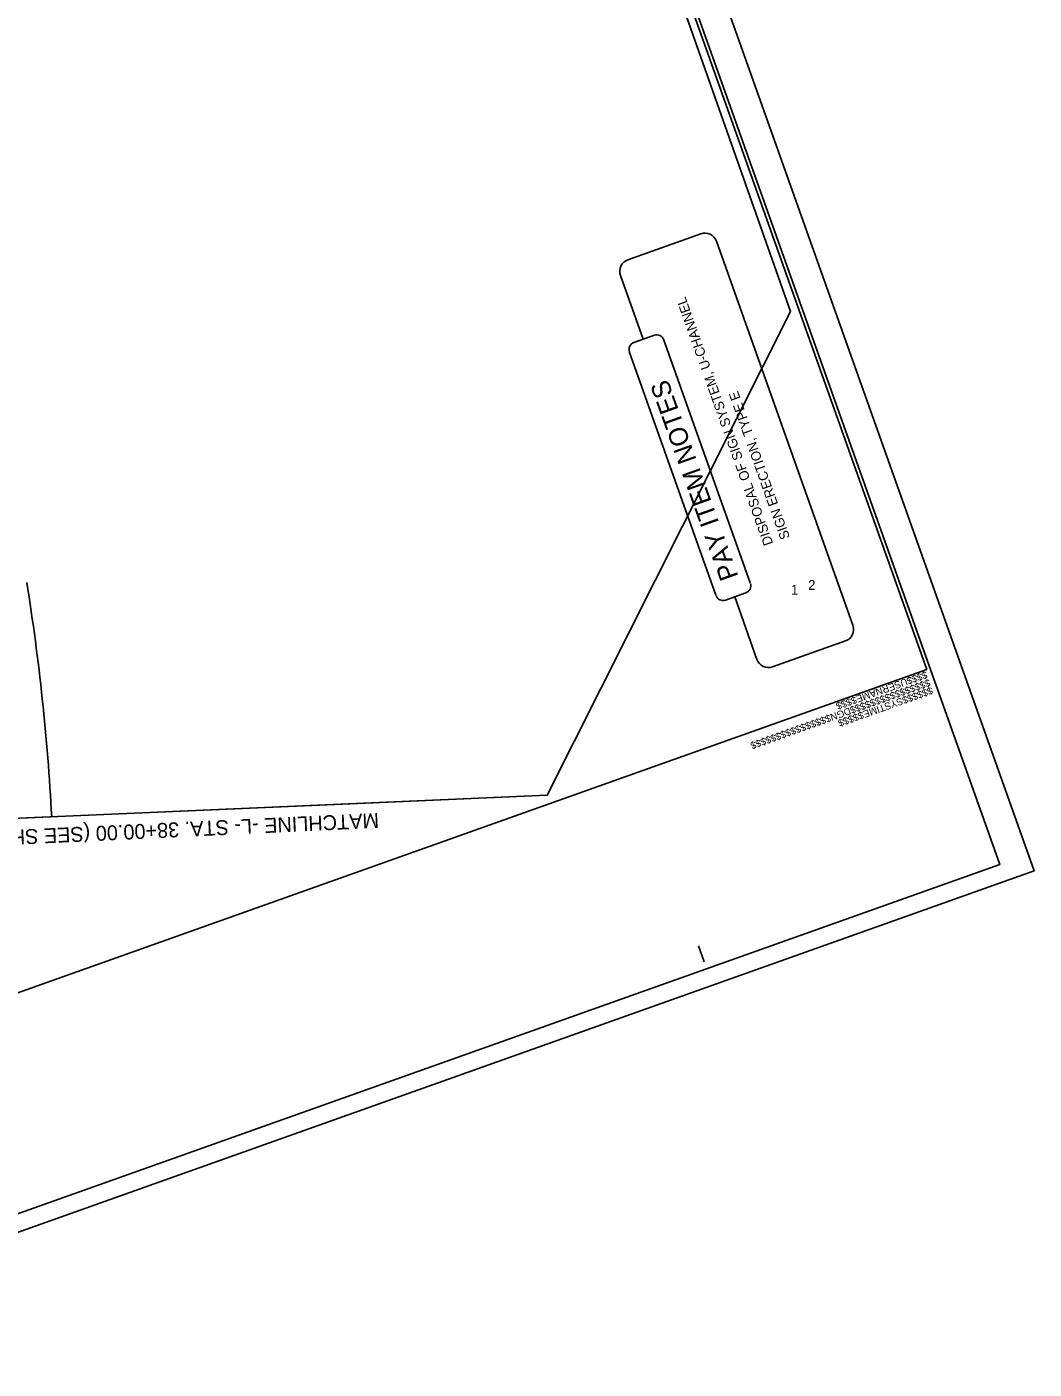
# Model space of a CAD drawing. Extents: x 1615843 to 1617444, y 901966 to 903921.
# Drawn here: x 1616698 to 1617444, y 901966 to 902958 of the extents above; entities that cross this region are included whole.
import ezdxf

# ---------------------------------------------------------------- set-up
doc = ezdxf.new("R2010")
doc.units = 0
for name, color, linetype in [('CTL Primary Horizontal and Vertical CELL', 7, 'Continuous'), ('CTL Primary Horizontal and Vertical Cogo Number', 7, 'Continuous'), ('CTL Secondary Horizontal and Vertical CELL', 7, 'Continuous'), ('Default', 7, 'Continuous'), ('Exist DTM Crownline Cogo Point CELL', 7, 'Continuous'), ('Exist DTM Regular Point CELL', 7, 'Continuous'), ('Exist Roads Curbs Cogo Number', 7, 'Continuous'), ('Exist Roads Curbs Cogo Point CELL', 7, 'Continuous'), ('Exist Structure Minor Pipes RCP 15 Inch Cogo Point CELL', 7, 'Continuous')]:
    doc.layers.add(name, color=color, linetype=linetype)

msp = doc.modelspace()

# ---------------------------------------------------------------- linework, layer by layer
at = {"layer": 'CTL Primary Horizontal and Vertical CELL'}
msp.add_lwpolyline([(1615865.68, 903555.66), (1616423.91, 901985.43), (1617418.05, 902338.86), (1616859.83, 903909.09)], close=True, dxfattribs=at)
at = {"layer": 'CTL Primary Horizontal and Vertical Cogo Number'}
msp.add_lwpolyline([(1615843.02, 903552.38), (1616407.11, 901965.67), (1617443.56, 902334.13), (1616879.47, 903920.85)], close=True, dxfattribs=at)
at = {"layer": 'CTL Secondary Horizontal and Vertical CELL'}
msp.add_line((1617199.45, 902266.98), (1617195.26, 902278.76), dxfattribs=at)
msp.add_lwpolyline([(1615872.27, 903544.74), (1616374.72, 902131.39), (1617364.06, 902483.11), (1616861.61, 903896.45)], close=True, dxfattribs=at)
at = {"layer": 'Exist DTM Crownline Cogo Point CELL'}
msp.add_lwpolyline([(1616920.55, 902382.99), (1616299.46, 902356.07), (1615953.12, 903334.31), (1616369.18, 903520.6), (1616903.33, 903759.78), (1617120.19, 903154.34), (1617263.37, 902747.79), (1617083.45, 902390.05)], close=True, dxfattribs=at)
at = {"layer": 'Exist DTM Regular Point CELL'}
msp.add_arc((1615052.19, 902285.31), 1667.02, 3.05543, 9.05, dxfattribs=at)
at = {"layer": 'Exist Roads Curbs Cogo Point CELL'}
msp.add_line((1616299.46, 902356.07), (1617083.45, 902390.05), dxfattribs=at)
at = {"layer": 'Exist Structure Minor Pipes RCP 15 Inch Cogo Point CELL'}
for p, q in [((1617196.98, 902805.27), (1617143.08, 902786.11)), ((1617309.54, 902515.8), (1617208.59, 902799.75)), ((1617154.33, 902727.33), (1617137.56, 902774.5)), ((1617162.61, 902730.28), (1617147.51, 902724.91)), ((1617230.33, 902539.8), (1617215.23, 902534.43)), ((1617238.51, 902490.55), (1617222.04, 902536.85)), ((1617304.02, 902504.19), (1617250.11, 902485.03))]:
    msp.add_line(p, q, dxfattribs=at)
for points in [[(1617233.49, 902547.19), (1617169.42, 902727.4)], [(1617208.11, 902538.17), (1617144.05, 902718.38)]]:
    msp.add_lwpolyline(points, dxfattribs=at)
for centre, radius, start, end in [((1617200.03, 902796.71), 9.09, 19.57069, 109.57069), ((1617146.12, 902777.54), 9.09, 109.57069, 199.57069), ((1617164.44, 902725.14), 5.45, 19.57069, 109.57069), ((1617149.34, 902719.77), 5.45, 109.57069, 199.57069), ((1617228.5, 902544.93), 5.45, 289.57069, 19.57069), ((1617213.4, 902539.57), 5.45, 199.57069, 289.57069), ((1617300.97, 902512.76), 9.09, 289.57069, 19.57069), ((1617247.07, 902493.59), 9.09, 199.57069, 289.57069)]:
    msp.add_arc(centre, radius, start, end, dxfattribs=at)

# ---------------------------------------------------------------- texts
at = {"layer": 'CTL Secondary Horizontal and Vertical CELL'}
for s, p in [('$$$$USERNAME$$$$', (1617363.45, 902481.99)), ('$$$$$$$$$$$$$$$$DGN$$$$$$$$$$$$$$$$', (1617365.66, 902476.09)), ('$$$$$$SYSTIME$$$$$', (1617367.5, 902470.32))]:
    msp.add_text(s, height=5.25, rotation=199.57069, dxfattribs=at).set_placement(p)
at = {"layer": 'Default'}
for s, height, rotation, p in [('DISPOSAL OF SIGN SYSTEM, U-CHANNEL', 7.1994, 109.57069, (1617250.6, 902576.26)), ('PAY ITEM NOTES', 13.8661, 109.75293, (1617224.99, 902551.9)), ('SIGN ERECTION, TYPE E', 7.1994, 109.57069, (1617263.05, 902580.69)), ('1', 7.2, 359.97341, (1617263.64, 902538.49)), ('2', 7.2, 359.97341, (1617276.42, 902542))]:
    msp.add_text(s, height=height, rotation=rotation, dxfattribs=at).set_placement(p)
at = {"layer": 'Exist Roads Curbs Cogo Number'}
msp.add_text('MATCHLINE -L- STA. 38+00.00 (SEE SHEET SIGN-4)', height=11, rotation=182.66245, dxfattribs=at).set_placement((1616958.66, 902377.04))

doc.saveas('drawing.dxf')
